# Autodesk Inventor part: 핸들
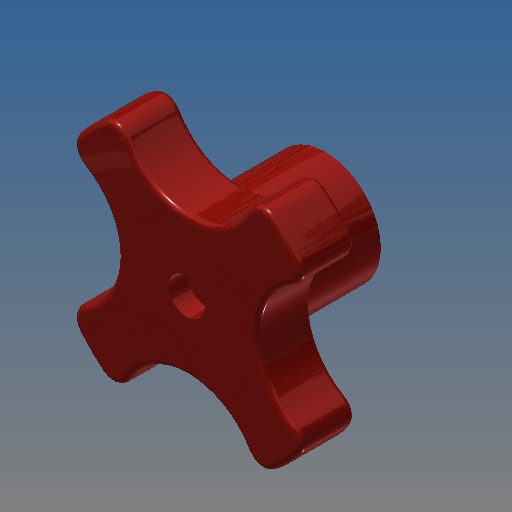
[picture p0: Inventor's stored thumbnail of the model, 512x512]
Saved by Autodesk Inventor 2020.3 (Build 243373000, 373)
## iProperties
Created: 2018-01
Part Number: 핸들
Material: ABS 플라스틱
Document SubType Name: Modeling
Designer: mduedu
Density: 1 g/cm^3
Appearance: 주황색-빨간색
Author: mduedu
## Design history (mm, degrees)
sketch "스케치1"
  geometry: C1 r 10 at (0, 0); C2 r 25 at (0, 0); 1 further point
  constraints: 2 centre point, 2 coincident
  dimensions: "d0" = 20 diameter of C1; "d1" = 50 diameter of C2
extrude "돌출1" new body sketch "스케치1" distance "d2" = 15; taper "d3" = 0 deg
extrude "돌출2" join sketch "스케치1" distance "d4" = 10; taper "d5" = 0 deg
sketch "스케치2" dims "d8" = 15
  geometry: L1 (-6, -6)-(-4.5, -6); L2 (6, -6)-(6, -4.5); L3 (6, 6)-(4.5, 6); L4 (-6, 6)-(-6, 4.5); L5 (-6, -6)-(6, 6); L6 (6, -6)-(-6, 6); L7 (-4.5, 6)-(-6, 6); L8 (4.5, 6)-(-4.5, 6); L9 (6, 4.5)-(6, 6); L10 (6, -4.5)-(6, 4.5); L11 (4.5, -6)-(6, -6); L12 (-4.5, -6)-(4.5, -6); L13 (-6, -4.5)-(-6, -6); L14 (-6, 4.5)-(-6, -4.5); 2 further points
  constraints: 28 end point, 18 parallel, 9 perpendicular, 3 horizontal, 2 midpoint, 1 coincident, 10 other
  dimensions: "d6" = 12 distance of L4.start L3.start; "d7" = 12 distance of L3.start L2.start
extrude "돌출3" cut sketch "스케치2" distance "d9" = 15; taper "d10" = 0 deg
sketch "스케치3"
  geometry: C1 r 12.5 at (25, 0); 2 further points
  constraints: 2 horizontal alignment, 1 centre point, 1 other
  dimensions: "d14" = 25 diameter of C1
extrude "돌출4" cut sketch "스케치3" extent not by distance; stored distance "d15" = 15; taper "d16" = 0 deg
fillet "모깎기1" dims "d20" = 3
fillet "모깎기2" dims "d24" = 1
sketch "스케치4"
  geometry: 2 further points
  constraints: 1 coincident
sketch "스케치5"
  geometry: 2 further points
  constraints: 1 coincident
hole "구멍1" sketch "스케치5" at (0, 0) diameter "d25" = 3.4; stored, may be unused: countersink angle "d29" = 90 deg, drill point angle "d31" = 0 deg; dims "d26" = 6, "d27" = 6.5, "d28" = 3.4, "d30" = 8
node "솔리드1"
pattern_circular "원형 패턴1" dims angle "d18" = 360 deg
pattern_circular "원형 패턴2" dims angle "d22" = 360 deg
node "투영된 루프1"
